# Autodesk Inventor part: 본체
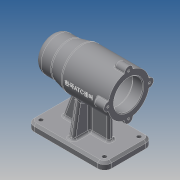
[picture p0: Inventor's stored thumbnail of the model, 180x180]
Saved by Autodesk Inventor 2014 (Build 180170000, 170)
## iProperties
Created: 2019-07
Part Number: 본체
Material: Generic
Document SubType Name: Modeling
Designer: kb542-18
Density: 1 g/cm^3
Appearance: Default
Author: kb542-18
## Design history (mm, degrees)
sketch "스케치1"
  geometry: L1 (-56, -35)-(56, -35); L2 (56, -35)-(56, 35); L3 (56, 35)-(-56, 35); L4 (-56, 35)-(-56, -35); L5 (-56, -35)-(56, 35); L6 (56, -35)-(-56, 35); 1 further point
  constraints: 12 end point, 2 midpoint, 2 parallel, 1 horizontal, 1 perpendicular
  dimensions: "d0" = 112 distance of L2.end L3.end; "d1" = 70 distance of L1.end L2.end
extrude "돌출1" new body sketch "스케치1" distance "d2" = 10; taper "d3" = 0 deg
sketch "스케치2"
  geometry: L1 (-56, 10)-(56, 10) reference; L2 (-56, 0)-(56, 0) reference; L3 (56, 80)-(-56, 80); L4 (56, 80)-(56, 105); L5 (56, 105)-(31, 105); L6 (31, 105)-(11, 110); L7 (11, 110)-(-56, 110); L8 (-56, 110)-(-56, 80); 1 further point
  constraints: 12 end point, 3 perpendicular, 2 parallel, 1 vertical alignment
  dimensions: "d4" = 112 distance of L3.start L3.end; "d5" = 25 distance from line of L5.end L4; "d6" = 45 distance from line of L4 L6.end; "d7" = 50 diameter of L5 L3; "d8" = 60 diameter of L7 L3; "d9" = 160 diameter of L2 L3
revolve "회전1" sketch "스케치2" stored, may be unused: angle "d10" = 90 deg
sketch "스케치13"
  geometry: L1 (56, -35)-(56, 35) reference; L2 (-56, 35)-(-56, -35) reference; L3 (-36, 4)-(31, 4); L4 (31, 4)-(31, -4); L5 (31, -4)-(-36, -4); L6 (-36, -4)-(-36, 4); 2 further points
  constraints: 8 end point, 2 parallel, 1 horizontal, 1 horizontal alignment, 1 midpoint, 1 perpendicular
  dimensions: "d86" = 20 distance between parallel lines of L2 L6; "d87" = 25 distance between parallel lines of L1 L4; "d88" = 8 distance of L3.end L4.end
extrude "돌출8" join sketch "스케치13" stored distance "d89" = 100; taper "d90" = 0 deg
sketch "스케치3"
  geometry: L1 (56, 55)-(56, 105) reference; L2 (-56, 50)-(-56, 110) reference; L3 (56, 80)-(-56, 80); L4 (50, 80)-(50, 90.5); L5 (50, 90.5)-(47, 90.5); L6 (47, 90.5)-(47, 96); L7 (47, 96)-(43, 96); L8 (43, 96)-(43, 97.5); L9 (43, 97.5)-(25, 97.5); L10 (25, 97.5)-(25, 101); L11 (25, 101)-(13, 101); L12 (13, 101)-(13, 104); L13 (13, 104)-(-41, 104); L14 (-41, 104)-(-41, 101); L15 (-41, 101)-(-56, 101); 1 further point
  constraints: 26 end point, 9 parallel, 3 perpendicular, 2 midpoint, 2 point on line
  dimensions: "d11" = 21 diameter of L5 L3; "d12" = 32 diameter of L7 L3; "d13" = 35 diameter of L9 L3; "d14" = 42 diameter of L11 L3; "d15" = 48 diameter of L13 L3; "d16" = 42 diameter of L15 L3; "d17" = 3 distance of L4.end L5.end; "d18" = 4 distance of L6.end L7.end; "d19" = 18 distance of L8.end L9.end; "d20" = 12 distance of L10.end L11.end; "d21" = 54 distance of L12.end L13.end; "d22" = 15 distance of L14.end L15.end
revolve "회전2" sketch "스케치3" stored, may be unused: angle "d23" = 90 deg
sketch "스케치4"
  geometry: C1 r 21 at (0, 0) reference; C2 r 6 at (-30, 0); C3 r 6 at (0, 30); C4 r 6 at (0, -30); C5 r 6 at (30, 0); A1 r 30 centre (0, 0) between (-30, 0) and (0, 30) reference; 1 further point
  constraints: 4 centre point, 4 point on circle, 2 horizontal alignment, 2 vertical alignment
  dimensions: "d24" = 12 diameter of C2; "d25" = 12 diameter of C3; "d26" = 12 diameter of C4; "d27" = 12 diameter of C5
extrude "돌출2" join sketch "스케치4" distance "d28" = 16; taper "d29" = 0 deg
sketch "스케치5"
  geometry: L1 (-56, -35)-(56, -35) reference; L2 (-4, 28)-(4, 28); L3 (4, 28)-(4, -28); L4 (4, -28)-(-4, -28); L5 (-4, -28)-(-4, 28); L6 (56, 35)-(-56, 35) reference; 2 further points
  constraints: 8 end point, 2 parallel, 1 horizontal, 1 midpoint, 1 perpendicular, 1 vertical alignment
  dimensions: "d30" = 7 distance between parallel lines of L1 L4; "d31" = 7 distance between parallel lines of L6 L2; "d32" = 8 distance of L2.start L2.end
extrude "돌출3" join sketch "스케치5" stored distance "d33" = 16; taper "d34" = 0 deg
sketch "스케치6"
  geometry: L1 (0, 0)-(-59.23, 0) reference; L2 (0, 56)-(-59.23, 56) reference; L3 (0, -7)-(0, 63) reference; L4 (0, 56)-(-47.334, 47.654); L5 (-47.334, 8.346)-(0, 0); A1 r 30 centre (-70, 28) between (-59.23, 0) and (-59.23, 56) reference; A2 r 30 centre (-70, 28) between (-40.6, 33.97) and (-64.03, 57.4) reference; A3 r 30 centre (-70, 28) between (-64.03, -1.4) and (-40.6, 22.03) reference; 1 further point
  constraints: 4 end point, 4 point on circle
  dimensions: "d35" = 100 deg angle of L3 L5; "d36" = 100 deg angle of L3 L4
extrude "돌출4" cut sketch "스케치6" stored distance "d37" = 16; taper "d38" = 0 deg
fillet "모깎기1" dims "d47" = 10
sketch "스케치10"
  geometry: C1 r 3 at (46, 25); C2 r 3 at (46, -25); C3 r 3 at (-46, 25); C4 r 3 at (-46, -25); A1 r 10 centre (-46, -25) between (-56, -25) and (-46, -35) reference; A2 r 10 centre (46, -25) between (46, -35) and (56, -25) reference; A3 r 10 centre (46, 25) between (56, 25) and (46, 35) reference; A4 r 10 centre (-46, 25) between (-46, 35) and (-56, 25) reference; 1 further point
  constraints: 4 centre point, 4 coincident
  dimensions: "d48" = 6 diameter of C1; "d49" = 6 diameter of C2; "d50" = 6 diameter of C3; "d51" = 6 diameter of C4
extrude "돌출7" cut sketch "스케치10" stored distance "d52" = 16; taper "d53" = 0 deg
fillet "모깎기2" dims "d54" = 10
sketch "스케치11"
  geometry: A1 r 6 centre (0, 0) between (0.6, 5.97) and (0.6, -5.97) reference; 2 further points
  constraints: 1 coincident
hole "구멍1" sketch "스케치11" at (0, 0) diameter "d55" = 3.242; stored, may be unused: countersink angle "d59" = 90 deg, drill point angle "d61" = 118 deg; dims "d56" = 8, "d57" = 4, "d58" = 2, "d60" = 11
fillet "모깎기4" dims "d66" = 0.3
fillet "모깎기5" dims "d67" = 3
fillet "모깎기6" dims "d68" = 3
chamfer "모따기1" distance "d69" = 1; stored, may be unused: second distance "d70" = 2, angle "d71" = 45 deg
fillet "모깎기7" dims "d72" = 3
fillet "모깎기8" dims "d73" = 1
chamfer "모따기2" distance "d74" = 3; stored, may be unused: second distance "d75" = 2, angle "d76" = 45 deg
fillet "모깎기9" dims "d77" = 3
fillet "모깎기10" dims "d78" = 3
chamfer "모따기3" distance "d79" = 1; stored, may be unused: second distance "d80" = 2, angle "d81" = 45 deg
node "작업 평면1"
sketch "스케치12"
  geometry: L1 (56, 109.226)-(56, 86.771) reference; L2 (56, 85.998)-(56, 74.002) reference; 3 further points
  constraints: 1 horizontal alignment, 1 midpoint, 1 other
  dimensions: "d83" = 42 distance from line of L1 point (14, 80)
feature "엠보싱1" sketch "스케치12" dims "d0" = 112, "d1" = 70, "d84" = 0.5, "d85" = 0
sketch "스케치14"
  geometry: L1 (0, 45.322)-(4, 45.322) reference; L2 (0, 0)-(0, 45.322) reference; L3 (15.527, 42.659)-(0, 0); L4 (82, 0)-(-10, 0) reference; 3 further points
  constraints: 2 end point, 3 other
  dimensions: "d91" = 110 deg angle of L4 L3
extrude "돌출9" cut sketch "스케치14" distance "d92" = 100; taper "d93" = 0 deg
fillet "모깎기11" dims "d94" = 3
fillet "모깎기12" dims "d95" = 3
fillet "모깎기13" dims "d96" = 3
node "솔리드1"
pattern_circular "원형 패턴1" dims angle "d63" = 360 deg
other parameters: "d82" = -30.5
